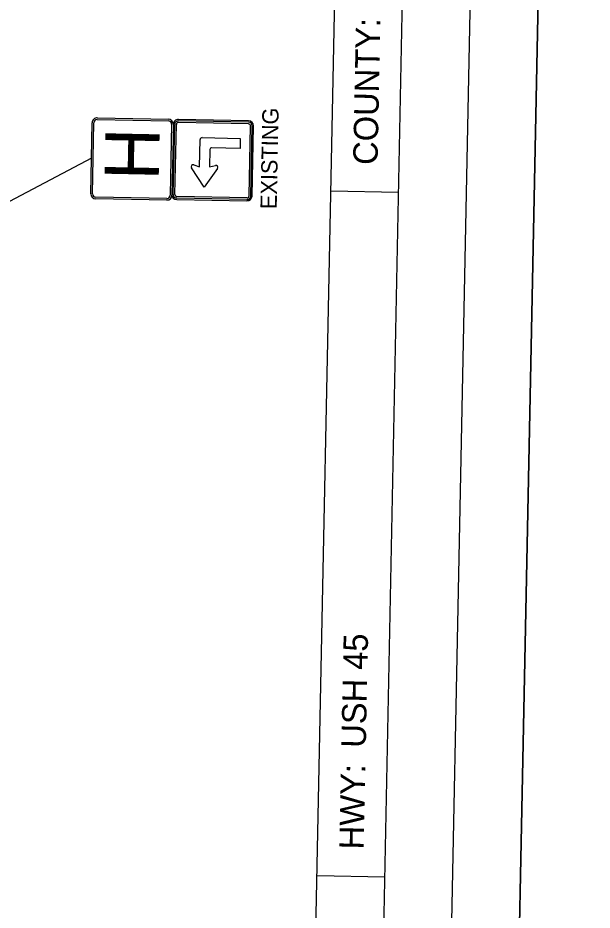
# Model space of a CAD drawing. Extents: x 311409 to 379449, y 121539 to 224848.
# Drawn here: x 366747 to 379449, y 144161 to 163905 of the extents above; entities that cross this region are included whole.
import ezdxf

# ---------------------------------------------------------------- set-up
doc = ezdxf.new("R2010")
doc.units = 0
for name, color, linetype in [('CA-TEXT', 7, 'Continuous'), ('E_SGN', 7, 'Continuous'), ('P_RDWY_Text', 7, 'Continuous'), ('PLT_Sheet_Border', 7, 'Continuous'), ('PLT_Sheet_Info', 7, 'Continuous')]:
    doc.layers.add(name, color=color, linetype=linetype)

msp = doc.modelspace()

# ---------------------------------------------------------------- linework, layer by layer
at = {"layer": 'CA-TEXT'}
msp.add_line((368375, 160799), (363309, 158127), dxfattribs=at)
at = {"layer": 'E_SGN'}
for p, q in [((368360, 160013), (368391, 161584)), ((368397, 160013), (368429, 161584)), ((368505, 161657), (370076, 161625)), ((368506, 161694), (370077, 161663)), ((370149, 161549), (370118, 159978)), ((370187, 161548), (370155, 159977)), ((370187, 161548), (370155, 159997)), ((370185, 159996), (370216, 161548)), ((370222, 159996), (370253, 161547)), ((371850, 161559), (370298, 161590)), ((371850, 161596), (370299, 161627)), ((371851, 161626), (370300, 161657)), ((371862, 159963), (371893, 161514)), ((371899, 159962), (371930, 161513)), ((371928, 159961), (371960, 161513)), ((370766, 160609), (370778, 161211)), ((370824, 161255), (371666, 161238)), ((371666, 161238), (371661, 161016)), ((370996, 160993), (370988, 160605)), ((371661, 161016), (371033, 161029)), ((370868, 160160), (370589, 160584)), ((370640, 160650), (370766, 160609)), ((371164, 160572), (370868, 160160)), ((370988, 160605), (371116, 160641)), ((370041, 159905), (368470, 159936)), ((371817, 159919), (370265, 159950)), ((370041, 159867), (368470, 159899)), ((370264, 159884), (371815, 159853)), ((371816, 159882), (370265, 159914))]:
    msp.add_line(p, q, dxfattribs=at)
for centre, radius, start, end in [((368503, 161582), 112, 88.8462, 178.8462), ((368503, 161582), 74.8, 88.8462, 178.8462), ((370074, 161551), 74.8, 358.8462, 88.8462), ((370074, 161551), 112, 358.8462, 88.8462), ((370297, 161546), 111, 88.8462, 178.8462), ((370297, 161546), 81.3, 88.8462, 178.8462), ((370297, 161546), 44.3, 88.8462, 178.8462), ((371849, 161515), 81.3, 358.8462, 88.8462), ((371849, 161515), 44.3, 358.8462, 88.8462), ((371849, 161515), 111, 358.8462, 88.8462), ((370823, 161210), 44.3, 88.8462, 178.8462), ((371033, 160992), 36.9, 88.8462, 178.8462), ((370626, 160608), 44.3, 72.0436, 213.3759), ((371128, 160598), 44.3, 324.3166, 105.6488), ((368472, 160011), 112, 178.8462, 268.8462), ((368472, 160011), 74.8, 178.8462, 268.8462), ((370043, 159980), 74.8, 268.8462, 358.8462), ((370043, 159980), 112, 268.8462, 358.8462), ((370266, 159995), 111, 178.8462, 268.8462), ((370266, 159995), 81.3, 178.8462, 268.8462), ((370266, 159995), 44.3, 178.8462, 268.8462), ((371817, 159964), 111, 268.8462, 358.8462), ((371817, 159964), 81.3, 268.8462, 358.8462), ((371817, 159964), 44.3, 268.8462, 358.8462)]:
    msp.add_arc(centre, radius, start, end, dxfattribs=at)
at = {"layer": 'P_RDWY_Text'}
msp.add_lwpolyline([(311409, 122868), (313463, 224848), (379449, 223519), (377396, 121539)], close=True, dxfattribs=at)
at = {"layer": 'PLT_Sheet_Border'}
for points in [[(377396, 121539), (379449, 223519), (313463, 224848), (311409, 122868)], [(375910, 122290), (377910, 221569), (314923, 222838), (312923, 123558)]]:
    msp.add_lwpolyline(points, close=True, dxfattribs=at)
at = {"layer": 'PLT_Sheet_Info'}
for p, q in [((372973, 125424), (374876, 219905)), ((374473, 125394), (376375, 219875)), ((375170, 160037), (373671, 160067)), ((374865, 144890), (373366, 144920))]:
    msp.add_line(p, q, dxfattribs=at)

# ---------------------------------------------------------------- texts
at = {"layer": 'CA-TEXT'}
msp.add_text('EXISTING', height=360, rotation=88.8468, dxfattribs=at).set_placement((372472, 159669))
at = {"layer": 'E_SGN'}
msp.add_text('H', height=1197, rotation=88.8462, dxfattribs=at).set_placement((369862, 160301))
at = {"layer": 'PLT_Sheet_Info'}
for s, p in [('COUNTY:', (374702, 160647)), ('USH 45         ', (374443, 147749)), ('HWY:', (374397, 145500))]:
    msp.add_text(s, height=540, rotation=88.8462, dxfattribs=at).set_placement(p)

doc.saveas('drawing.dxf')
